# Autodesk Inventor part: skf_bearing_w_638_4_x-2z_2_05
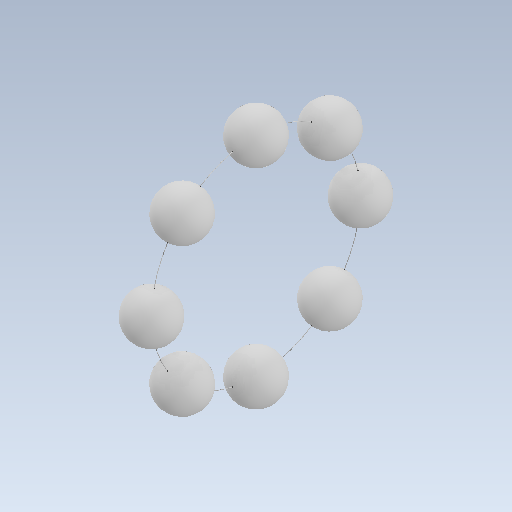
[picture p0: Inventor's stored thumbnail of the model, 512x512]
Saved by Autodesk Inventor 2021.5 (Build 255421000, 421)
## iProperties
Created: 2023-12
Part Number: skf_bearing_w_638_4_x-2z_2_05
Checked By: TraceParts S.A.
Material: Generic
Catalog Web Link: www.traceparts.com
Document SubType Name: Modeling
Designer: TraceParts
Density: 1 g/cm^3
Appearance: Default
Company: TraceParts S.A.
Author: TraceParts
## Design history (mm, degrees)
feature "skf_bearing_w_638_4_x-2z_2_05.ipt"
body "Solid1"
